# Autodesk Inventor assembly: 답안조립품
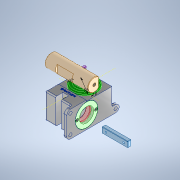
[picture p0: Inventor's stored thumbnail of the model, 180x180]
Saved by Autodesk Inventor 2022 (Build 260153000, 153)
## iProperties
Created: 2023-09
Part Number: 답안조립품
Document SubType Name: Assembly
Designer: PC-13
Author: PC-13
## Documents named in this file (11)
- C:\Users\PC-13\Desktop\730906V1010\답안조립품.iam
- C:\Users\PC-13\Desktop\730906V1010\본체.ipt
- C:\Users\PC-13\Desktop\730906V1010\가이드 부시.ipt
- C:\Users\PC-13\Desktop\730906V1010\부시 커버.ipt
- C:\Users\PC-13\Desktop\730906V1010\볼트 M4.ipt
- C:\Users\PC-13\Desktop\730906V1010\래크.ipt
- C:\Users\PC-13\Desktop\730906V1010\스톱퍼.ipt
- C:\Users\PC-13\Desktop\730906V1010\베어링 6003.ipt
- C:\Users\PC-13\Desktop\730906V1010\피니언.ipt
- C:\Users\PC-13\Desktop\730906V1010\앞커버.ipt
- C:\Users\PC-13\Desktop\730906V1010\오일 실 17 30 5.ipt
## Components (3 placed, 2 different names)
1. 가이드 부시:1
2. 가이드 부시:2
3. 피니언:1
